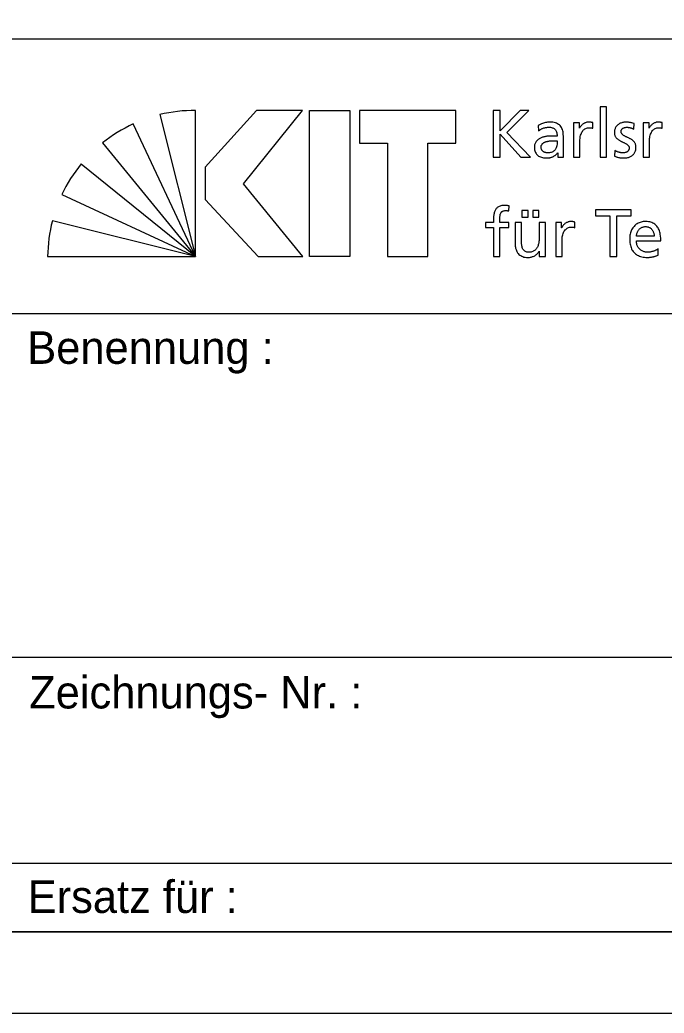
# Model space of a CAD drawing. Extents: x 0 to 29.7, y 0 to 21.
# Drawn here: x 27.516 to 28.508, y 0 to 1.529 of the extents above; entities that cross this region are included whole.
import ezdxf

# ---------------------------------------------------------------- set-up
doc = ezdxf.new("R2010")
doc.units = 0
doc.layers.add('90_Plankopf', color=7, linetype='Continuous')

msp = doc.modelspace()

# ---------------------------------------------------------------- linework, layer by layer
at = {"layer": '90_Plankopf'}
for p, q in [((25.153, 1.4998), (29.6, 1.4998)), ((25.153, 1.4998), (29.6, 1.4998)), ((27.7319, 1.3833), (27.787, 1.1647)), ((27.787, 1.1647), (27.787, 1.3896)), ((28.2452, 1.3897), (28.2452, 1.3176)), ((27.787, 1.1647), (27.6908, 1.3688)), ((28.3145, 1.3665), (28.315, 1.3583)), ((28.3982, 1.3621), (28.3982, 1.3708)), ((28.4614, 1.361), (28.4622, 1.3694)), ((28.5053, 1.3621), (28.5053, 1.3708)), ((28.353, 1.328), (28.353, 1.3497)), ((27.6436, 1.3396), (27.787, 1.1647)), ((28.3433, 1.3427), (28.3433, 1.3381)), ((28.2452, 1.3176), (28.2556, 1.3176)), ((28.2876, 1.3176), (28.3027, 1.3176)), ((28.4324, 1.328), (28.4319, 1.3193)), ((27.787, 1.1647), (27.6108, 1.3071)), ((27.581, 1.2603), (27.787, 1.1647)), ((28.2693, 1.2348), (28.2697, 1.2427)), ((27.787, 1.1647), (27.5664, 1.2197)), ((28.3707, 1.2091), (28.3707, 1.2178)), ((28.4927, 1.196), (28.4654, 1.196)), ((28.4654, 1.1888), (28.503, 1.1888)), ((27.5591, 1.1647), (27.787, 1.1647)), ((28.4989, 1.1668), (28.4989, 1.1765)), ((27.5, 1.0768), (29.6, 1.0768)), ((27.5, 0.548), (29.6, 0.548)), ((27.5, 0.2308), (29.6, 0.2308)), ((29.6, 0.125), (25.153, 0.125)), ((25.445, 0.125), (29.6, 0.125)), ((25.445, 0.125), (29.6, 0.125))]:
    msp.add_line(p, q, dxfattribs=at)
for points in [[(0, 0), (29.725, 0), (29.725, 21.025), (0, 21.025)], [(0.625, 0.125), (29.6, 0.125), (29.6, 20.9), (0.625, 20.9)], [(27.9517, 1.3897), (27.8809, 1.3897), (27.8018, 1.3025), (27.8018, 1.2523), (27.8834, 1.1647), (27.9521, 1.1647), (27.8606, 1.2766)], [(28.0243, 1.3897), (28.0243, 1.1647), (27.9625, 1.1647), (27.9625, 1.3897)], [(28.0391, 1.3897), (28.0391, 1.339), (28.0825, 1.339), (28.0825, 1.1647), (28.1443, 1.1647), (28.1443, 1.339), (28.1877, 1.339), (28.1877, 1.3897)]]:
    msp.add_lwpolyline(points, close=True, dxfattribs=at)
for points in [[(28.4095, 1.3176), (28.4192, 1.3176), (28.4192, 1.395), (28.4095, 1.395), (28.4095, 1.3176)], [(28.3027, 1.3176), (28.2662, 1.3556), (28.3, 1.3897), (28.2863, 1.3897), (28.2556, 1.358), (28.2556, 1.3897), (28.2452, 1.3897)], [(28.378, 1.3621), (28.3778, 1.3621), (28.3778, 1.3703), (28.3688, 1.3703), (28.3688, 1.3176), (28.3785, 1.3176), (28.3785, 1.3416)], [(28.4852, 1.3621), (28.485, 1.3621), (28.485, 1.3703), (28.4759, 1.3703), (28.4759, 1.3176), (28.4856, 1.3176), (28.4856, 1.3416)], [(28.2556, 1.3176), (28.2556, 1.3529), (28.2876, 1.3176)], [(28.3441, 1.3245), (28.3443, 1.3245), (28.3443, 1.3176), (28.3534, 1.3176)], [(28.2889, 1.2356), (28.2889, 1.2253), (28.2986, 1.2253), (28.2986, 1.2356), (28.2889, 1.2356)], [(28.3058, 1.2356), (28.3058, 1.2253), (28.3155, 1.2253), (28.3155, 1.2356), (28.3058, 1.2356)], [(28.4248, 1.1647), (28.4351, 1.1647), (28.4351, 1.2276), (28.4575, 1.2276), (28.4575, 1.2367), (28.4024, 1.2367), (28.4024, 1.2276), (28.4248, 1.2276), (28.4248, 1.1647)], [(28.2456, 1.2221), (28.2456, 1.2173), (28.2332, 1.2173), (28.2332, 1.2094), (28.2456, 1.2094), (28.2456, 1.1647), (28.2553, 1.1647), (28.2553, 1.2094), (28.2692, 1.2094), (28.2692, 1.2173), (28.2553, 1.2173), (28.2553, 1.223)], [(28.2885, 1.19), (28.2885, 1.2173), (28.2788, 1.2173), (28.2788, 1.186)], [(28.3254, 1.1647), (28.3254, 1.2173), (28.3157, 1.2173), (28.3157, 1.1929)], [(28.3506, 1.2091), (28.3504, 1.2091), (28.3504, 1.2173), (28.3413, 1.2173), (28.3413, 1.1647), (28.351, 1.1647), (28.351, 1.1886)], [(28.3158, 1.173), (28.316, 1.173), (28.316, 1.1647), (28.3254, 1.1647)]]:
    msp.add_lwpolyline(points, dxfattribs=at)
for centre, start, end in [((27.7862, 1.1514), 89.8053, 103.1895), ((27.7915, 1.1529), 115.0126, 128.3968), ((27.7954, 1.1566), 140.7898, 154.174), ((27.7973, 1.1609), 165.7222, 179.1064)]:
    msp.add_arc(centre, 0.2382, start, end, dxfattribs=at)
for points in [[(28.353, 1.3497), (28.353, 1.3545), (28.3523, 1.3585), (28.3508, 1.3617), (28.3494, 1.365), (28.3471, 1.3674), (28.344, 1.369), (28.3409, 1.3707), (28.3368, 1.3715), (28.3318, 1.3715), (28.3285, 1.3715), (28.3253, 1.371), (28.3224, 1.3701), (28.3195, 1.3692), (28.3169, 1.368), (28.3145, 1.3665)], [(28.315, 1.3583), (28.3163, 1.3594), (28.3178, 1.3604), (28.3195, 1.3611), (28.3211, 1.362), (28.3229, 1.3626), (28.3247, 1.363), (28.3266, 1.3634), (28.3284, 1.3637), (28.3303, 1.3637), (28.3335, 1.3637), (28.336, 1.3631), (28.3379, 1.3621), (28.3399, 1.3611), (28.3412, 1.3596), (28.342, 1.3575), (28.3429, 1.3555), (28.3433, 1.353), (28.3433, 1.3499)], [(28.3982, 1.3708), (28.3975, 1.3709), (28.3968, 1.371), (28.3962, 1.3712), (28.3956, 1.3713), (28.3949, 1.3713), (28.3942, 1.3714), (28.3935, 1.3715), (28.3927, 1.3715), (28.3918, 1.3715), (28.3899, 1.3715), (28.3881, 1.3711), (28.3863, 1.3703), (28.3845, 1.3695), (28.3829, 1.3684), (28.3815, 1.367), (28.3801, 1.3656), (28.3789, 1.3639), (28.378, 1.3621)], [(28.3785, 1.3416), (28.3785, 1.346), (28.3791, 1.3498), (28.3802, 1.353), (28.3814, 1.3562), (28.3831, 1.3587), (28.3852, 1.3604), (28.3874, 1.3621), (28.3899, 1.363), (28.3928, 1.363), (28.3936, 1.3631), (28.3945, 1.363), (28.3954, 1.3629), (28.3964, 1.3627), (28.3973, 1.3625), (28.3982, 1.3621)], [(28.4622, 1.3694), (28.4604, 1.37), (28.4584, 1.3705), (28.4565, 1.3709), (28.4545, 1.3713), (28.4524, 1.3715), (28.4502, 1.3715), (28.4476, 1.3715), (28.4451, 1.3712), (28.4429, 1.3705), (28.4406, 1.3698), (28.4387, 1.3688), (28.437, 1.3675), (28.4353, 1.3662), (28.434, 1.3645), (28.433, 1.3625), (28.4321, 1.3604), (28.4316, 1.358), (28.4316, 1.3553), (28.4316, 1.3532), (28.4321, 1.3514), (28.4329, 1.3498), (28.4337, 1.3483), (28.4348, 1.347), (28.4361, 1.3459), (28.4375, 1.3447), (28.439, 1.3437), (28.4406, 1.3429), (28.4422, 1.342), (28.4438, 1.3412), (28.4454, 1.3404), (28.4471, 1.3397), (28.4485, 1.3389), (28.4499, 1.338), (28.4512, 1.3373), (28.4523, 1.3363), (28.4532, 1.3353), (28.454, 1.3343), (28.4544, 1.3331), (28.4544, 1.3318), (28.4544, 1.3304), (28.4541, 1.3292), (28.4535, 1.3282), (28.4529, 1.3272), (28.4521, 1.3265), (28.4511, 1.3259), (28.4501, 1.3253), (28.4491, 1.3249), (28.4479, 1.3246), (28.4468, 1.3244), (28.4456, 1.3242), (28.4445, 1.3242), (28.4435, 1.3242), (28.4424, 1.3244), (28.441, 1.3247), (28.4396, 1.3249), (28.4381, 1.3253), (28.4366, 1.3259), (28.4351, 1.3265), (28.4337, 1.3271), (28.4324, 1.328)], [(28.4319, 1.3193), (28.4342, 1.3181), (28.4365, 1.3174), (28.4389, 1.317), (28.4414, 1.3166), (28.4439, 1.3164), (28.4464, 1.3164), (28.4487, 1.3164), (28.451, 1.3167), (28.4532, 1.3174), (28.4554, 1.318), (28.4573, 1.3191), (28.4591, 1.3204), (28.4608, 1.3217), (28.4622, 1.3234), (28.4632, 1.3255), (28.4642, 1.3276), (28.4647, 1.33), (28.4647, 1.3328), (28.4647, 1.3352), (28.4643, 1.3372), (28.4635, 1.3389), (28.4626, 1.3406), (28.4616, 1.342), (28.4602, 1.3431), (28.4589, 1.3443), (28.4574, 1.3453), (28.4557, 1.3461), (28.4541, 1.3469), (28.4525, 1.3477), (28.4509, 1.3484), (28.4493, 1.3491), (28.4478, 1.3499), (28.4464, 1.3507), (28.4451, 1.3515), (28.444, 1.3524), (28.4432, 1.3534), (28.4424, 1.3545), (28.4419, 1.3557), (28.4419, 1.3573), (28.4419, 1.3587), (28.4424, 1.3599), (28.4432, 1.3609), (28.4441, 1.3618), (28.4452, 1.3625), (28.4466, 1.363), (28.448, 1.3634), (28.4495, 1.3637), (28.4512, 1.3637), (28.4518, 1.3637), (28.4526, 1.3636), (28.4535, 1.3634), (28.4544, 1.3633), (28.4553, 1.3631), (28.4564, 1.3628), (28.4574, 1.3626), (28.4583, 1.3623), (28.4592, 1.362), (28.4601, 1.3616), (28.4609, 1.3613), (28.4614, 1.361)], [(28.5053, 1.3708), (28.5046, 1.3709), (28.504, 1.371), (28.5034, 1.3712), (28.5027, 1.3713), (28.5021, 1.3713), (28.5014, 1.3714), (28.5007, 1.3715), (28.4998, 1.3715), (28.4989, 1.3715), (28.497, 1.3715), (28.4952, 1.3711), (28.4934, 1.3703), (28.4917, 1.3695), (28.4901, 1.3684), (28.4886, 1.367), (28.4872, 1.3656), (28.486, 1.3639), (28.4852, 1.3621)], [(28.4856, 1.3416), (28.4856, 1.346), (28.4862, 1.3498), (28.4874, 1.353), (28.4886, 1.3562), (28.4902, 1.3587), (28.4923, 1.3604), (28.4945, 1.3621), (28.497, 1.363), (28.4999, 1.363), (28.5008, 1.3631), (28.5016, 1.363), (28.5026, 1.3629), (28.5035, 1.3627), (28.5044, 1.3625), (28.5053, 1.3621)], [(28.3433, 1.3499), (28.342, 1.35), (28.3408, 1.3501), (28.3397, 1.3501), (28.3386, 1.3501), (28.3376, 1.3501), (28.3365, 1.3501), (28.3354, 1.3501), (28.3342, 1.3501), (28.3329, 1.3501), (28.3309, 1.3501), (28.3288, 1.35), (28.3266, 1.3496), (28.3243, 1.3492), (28.3221, 1.3487), (28.32, 1.3478), (28.3179, 1.347), (28.316, 1.346), (28.3142, 1.3446), (28.3125, 1.3433), (28.3111, 1.3416), (28.3101, 1.3397), (28.309, 1.3377), (28.3085, 1.3354), (28.3085, 1.3328), (28.3085, 1.329), (28.3094, 1.3259), (28.311, 1.3235), (28.3126, 1.3211), (28.3149, 1.3193), (28.3177, 1.3181), (28.3206, 1.317), (28.324, 1.3164), (28.3278, 1.3164), (28.33, 1.3164), (28.332, 1.3167), (28.3338, 1.3172), (28.3355, 1.3177), (28.3371, 1.3184), (28.3384, 1.3192), (28.3398, 1.32), (28.3409, 1.3209), (28.3418, 1.3218), (28.3428, 1.3228), (28.3435, 1.3236), (28.3441, 1.3245)], [(28.3433, 1.3381), (28.3433, 1.3354), (28.3427, 1.3331), (28.3416, 1.331), (28.3405, 1.3289), (28.3388, 1.3273), (28.3367, 1.3261), (28.3345, 1.3249), (28.3318, 1.3243), (28.3286, 1.3242), (28.3275, 1.3242), (28.3264, 1.3244), (28.3252, 1.3248), (28.3241, 1.3252), (28.323, 1.3257), (28.322, 1.3264), (28.3211, 1.3272), (28.3203, 1.3281), (28.3197, 1.3291), (28.3191, 1.3302), (28.3188, 1.3314), (28.3188, 1.3328), (28.3188, 1.3347), (28.3193, 1.3362), (28.3202, 1.3374), (28.3211, 1.3387), (28.3223, 1.3396), (28.3237, 1.3404), (28.3252, 1.3411), (28.3267, 1.3417), (28.3284, 1.342), (28.33, 1.3424), (28.3316, 1.3426), (28.3332, 1.3428), (28.3347, 1.3429), (28.336, 1.3429), (28.3371, 1.3429), (28.3381, 1.3429), (28.3391, 1.3429), (28.3402, 1.3428), (28.3412, 1.3428), (28.3422, 1.3427), (28.3433, 1.3427)], [(28.3534, 1.3176), (28.3533, 1.3181), (28.3532, 1.3188), (28.3532, 1.3197), (28.3531, 1.3205), (28.3531, 1.3216), (28.353, 1.323), (28.353, 1.3243), (28.353, 1.326), (28.353, 1.328)], [(28.2697, 1.2427), (28.2688, 1.2428), (28.2678, 1.243), (28.2667, 1.2431), (28.2656, 1.2432), (28.2645, 1.2433), (28.2632, 1.2433), (28.2597, 1.2433), (28.2568, 1.2428), (28.2544, 1.2418), (28.2521, 1.2408), (28.2503, 1.2394), (28.2491, 1.2375), (28.2478, 1.2356), (28.2469, 1.2334), (28.2464, 1.2308), (28.2458, 1.2282), (28.2456, 1.2253), (28.2456, 1.2221)], [(28.2553, 1.223), (28.2553, 1.2247), (28.2554, 1.2264), (28.2556, 1.2279), (28.2558, 1.2294), (28.2562, 1.2307), (28.2569, 1.2319), (28.2575, 1.233), (28.2585, 1.2339), (28.2597, 1.2345), (28.261, 1.2351), (28.2626, 1.2354), (28.2647, 1.2354), (28.2655, 1.2354), (28.2664, 1.2354), (28.2672, 1.2353), (28.268, 1.2352), (28.2688, 1.235), (28.2693, 1.2348)], [(28.3707, 1.2178), (28.37, 1.2179), (28.3693, 1.2181), (28.3688, 1.2182), (28.3681, 1.2183), (28.3675, 1.2184), (28.3667, 1.2184), (28.3661, 1.2185), (28.3652, 1.2185), (28.3643, 1.2185), (28.3624, 1.2185), (28.3606, 1.2181), (28.3588, 1.2173), (28.3571, 1.2165), (28.3555, 1.2154), (28.354, 1.214), (28.3526, 1.2126), (28.3514, 1.211), (28.3506, 1.2091)], [(28.351, 1.1886), (28.351, 1.193), (28.3516, 1.1968), (28.3528, 1.2), (28.3539, 1.2032), (28.3556, 1.2057), (28.3577, 1.2074), (28.3599, 1.2092), (28.3624, 1.21), (28.3653, 1.21), (28.3662, 1.2101), (28.367, 1.21), (28.368, 1.2099), (28.3689, 1.2097), (28.3698, 1.2095), (28.3707, 1.2091)], [(28.503, 1.1888), (28.503, 1.1931), (28.5026, 1.197), (28.5018, 1.2006), (28.501, 1.2042), (28.4997, 1.2073), (28.4979, 1.21), (28.4961, 1.2127), (28.4938, 1.2148), (28.4908, 1.2162), (28.4878, 1.2177), (28.4841, 1.2185), (28.4797, 1.2185), (28.476, 1.2185), (28.4726, 1.2178), (28.4696, 1.2166), (28.4666, 1.2152), (28.464, 1.2134), (28.4618, 1.2111), (28.4597, 1.2087), (28.458, 1.2059), (28.4569, 1.2026), (28.4557, 1.1994), (28.4551, 1.1958), (28.4551, 1.1919), (28.4551, 1.1876), (28.4556, 1.1837), (28.4567, 1.1802), (28.4578, 1.1767), (28.4595, 1.1737), (28.4617, 1.1712), (28.4639, 1.1687), (28.4668, 1.1668), (28.4702, 1.1655), (28.4736, 1.1641), (28.4777, 1.1634), (28.4823, 1.1634), (28.4852, 1.1634), (28.4876, 1.1636), (28.4897, 1.164), (28.4917, 1.1644), (28.4934, 1.1648), (28.4949, 1.1653), (28.4964, 1.1659), (28.4977, 1.1664), (28.4989, 1.1668)], [(28.4654, 1.196), (28.4656, 1.1977), (28.466, 1.1995), (28.4666, 1.2012), (28.4672, 1.2029), (28.4681, 1.2045), (28.4692, 1.2059), (28.4703, 1.2073), (28.4717, 1.2085), (28.4734, 1.2093), (28.4751, 1.2102), (28.4772, 1.2107), (28.4795, 1.2107), (28.4816, 1.2107), (28.4835, 1.2103), (28.4851, 1.2095), (28.4867, 1.2088), (28.4881, 1.2077), (28.4892, 1.2064), (28.4903, 1.205), (28.4912, 1.2035), (28.4918, 1.2017), (28.4924, 1.1999), (28.4927, 1.1981), (28.4927, 1.196)], [(28.3157, 1.1929), (28.3157, 1.1897), (28.3154, 1.1868), (28.3147, 1.1841), (28.3141, 1.1815), (28.3131, 1.1792), (28.3118, 1.1773), (28.3105, 1.1754), (28.3088, 1.1739), (28.3068, 1.1728), (28.3048, 1.1718), (28.3024, 1.1713), (28.2997, 1.1713), (28.2969, 1.1714), (28.2947, 1.1722), (28.293, 1.1736), (28.2914, 1.175), (28.2902, 1.1771), (28.2895, 1.1798), (28.2889, 1.1825), (28.2885, 1.1859), (28.2885, 1.19)], [(28.2788, 1.186), (28.2788, 1.1813), (28.2795, 1.1772), (28.2809, 1.1739), (28.2823, 1.1705), (28.2845, 1.1679), (28.2874, 1.1661), (28.2903, 1.1644), (28.294, 1.1634), (28.2986, 1.1634), (28.301, 1.1634), (28.3034, 1.1638), (28.3056, 1.1646), (28.3079, 1.1653), (28.3099, 1.1665), (28.3117, 1.1679), (28.3134, 1.1693), (28.3148, 1.171), (28.3158, 1.173)], [(28.4989, 1.1765), (28.4983, 1.176), (28.4975, 1.1755), (28.4963, 1.1749), (28.4952, 1.1743), (28.4939, 1.1737), (28.4924, 1.1732), (28.4909, 1.1726), (28.4893, 1.1722), (28.4876, 1.1718), (28.486, 1.1715), (28.4844, 1.1713), (28.4827, 1.1713), (28.4804, 1.1713), (28.4782, 1.1717), (28.4762, 1.1725), (28.4741, 1.1734), (28.4722, 1.1746), (28.4706, 1.1761), (28.469, 1.1777), (28.4677, 1.1795), (28.4668, 1.1817), (28.4659, 1.1838), (28.4654, 1.1862), (28.4654, 1.1888)]]:
    msp.add_open_spline(points, degree=3, dxfattribs=at)

# ---------------------------------------------------------------- texts
for s, p in [('Benennung :', (27.5278, 0.9995)), ('Zeichnungs- Nr. :', (27.5307, 0.469)), ('Ersatz für :', (27.5285, 0.1542))]:
    msp.add_text(s, height=0.05, dxfattribs=at).set_placement(p)

doc.saveas('drawing.dxf')
